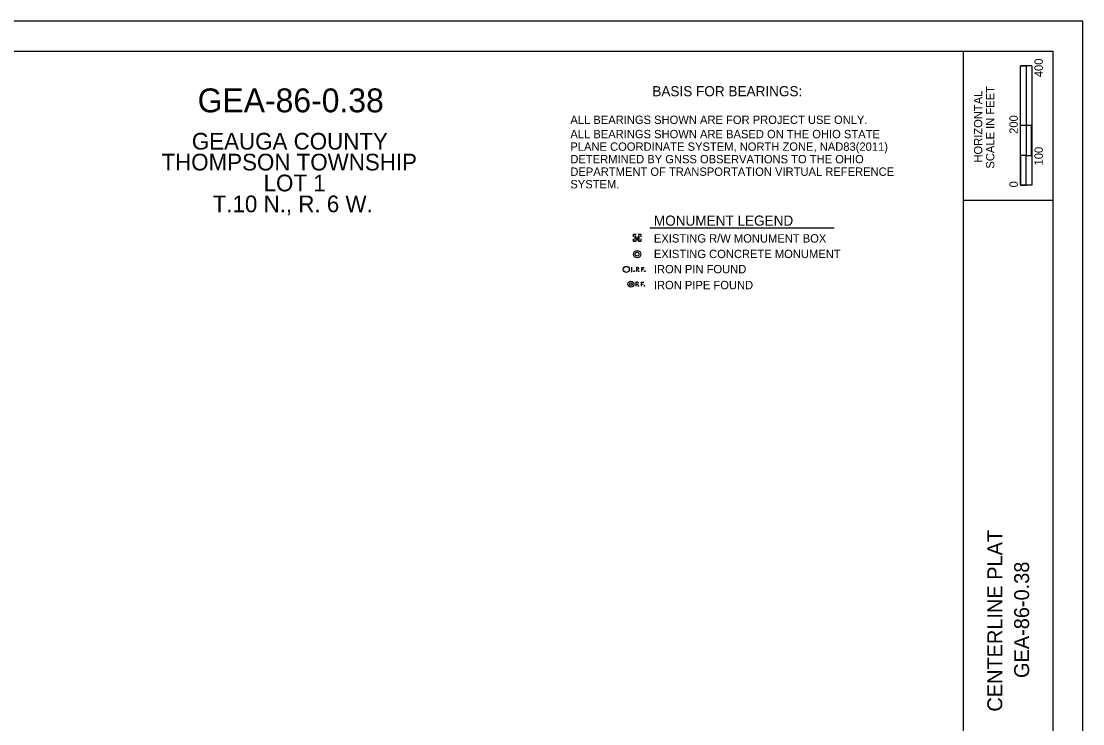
# Model space of a CAD drawing. Extents: x -0.2 to 34, y 0 to 22.
# Drawn here: x 16.2 to 34, y 10.22 to 22 of the extents above; entities that cross this region are included whole.
import ezdxf

# ---------------------------------------------------------------- set-up
doc = ezdxf.new("R2010")
doc.units = 0
for name, color, linetype in [('SH_Border', 7, 'Continuous'), ('SH_Cut_Line', 7, 'Continuous'), ('SH_Data', 7, 'Continuous'), ('SH_Text', 7, 'Continuous')]:
    doc.layers.add(name, color=color, linetype=linetype)

msp = doc.modelspace()

# ---------------------------------------------------------------- linework, layer by layer
at = {"layer": 'SH_Border'}
for p, q in [((32, 0.5), (32, 21.5)), ((32, 19), (33.5, 19))]:
    msp.add_line(p, q, dxfattribs=at)
msp.add_lwpolyline([(1.5, 21.5), (33.5, 21.5), (33.5, 0.5), (1.5, 0.5)], close=True, dxfattribs=at)
at = {"layer": 'SH_Cut_Line'}
msp.add_lwpolyline([(0, 0), (34, 0), (34, 22), (0, 22)], close=True, dxfattribs=at)
at = {"layer": 'SH_Data'}
for p, q in [((32.957, 19.25), (32.957, 21.25)), ((33.144, 21.25), (32.957, 21.25)), ((32.957, 20.25), (32.957, 21.25)), ((32.957, 21.25), (33.05, 21.25)), ((33.05, 21.25), (33.051, 21.25)), ((33.051, 21.25), (33.051, 20.25)), ((33.144, 21.25), (33.144, 19.25)), ((33.051, 20.25), (32.957, 20.25)), ((33.143, 20.25), (33.05, 20.25)), ((33.05, 20.25), (33.05, 19.75)), ((33.143, 19.75), (33.143, 20.25)), ((33.05, 19.75), (32.957, 19.75)), ((32.957, 19.75), (32.957, 19.25)), ((33.05, 19.25), (33.05, 19.75)), ((33.05, 19.75), (33.143, 19.75)), ((33.144, 19.25), (32.957, 19.25)), ((32.957, 19.25), (33.05, 19.25))]:
    msp.add_line(p, q, dxfattribs=at)
at = {"layer": 'SH_Text'}
for p, q in [((26.739, 18.534), (29.832, 18.534)), ((26.527, 18.368), (26.527, 18.368)), ((26.429, 17.873), (26.445, 17.873)), ((26.429, 17.873), (26.445, 17.873)), ((26.429, 17.806), (26.445, 17.806)), ((26.437, 17.806), (26.437, 17.873)), ((26.514, 17.841), (26.54, 17.841)), ((26.607, 17.806), (26.607, 17.873)), ((26.607, 17.873), (26.646, 17.873)), ((26.607, 17.841), (26.635, 17.841)), ((26.6, 17.559), (26.6, 17.625)), ((26.6, 17.625), (26.638, 17.625)), ((26.506, 17.593), (26.533, 17.593)), ((26.6, 17.593), (26.627, 17.593))]:
    msp.add_line(p, q, dxfattribs=at)
for points in [[(26.465, 18.383), (26.465, 18.43), (26.512, 18.43)], [(26.512, 18.305), (26.465, 18.305), (26.465, 18.352)], [(26.496, 18.326), (26.496, 18.409), (26.527, 18.326), (26.558, 18.409), (26.558, 18.326)], [(26.542, 18.43), (26.59, 18.43), (26.59, 18.383)], [(26.59, 18.352), (26.59, 18.305), (26.542, 18.305)], [(26.54, 17.873), (26.514, 17.873), (26.514, 17.806)], [(26.533, 17.625), (26.506, 17.625), (26.506, 17.559)]]:
    msp.add_lwpolyline(points, dxfattribs=at)
for centre, radius in [((26.527, 18.095), 0.0625), ((26.527, 18.095), 0.0333), ((26.345, 17.84), 0.05), ((26.477, 17.811), 0.00583), ((26.554, 17.811), 0.00583), ((26.656, 17.811), 0.00583), ((26.423, 17.592), 0.05), ((26.423, 17.592), 0.0206), ((26.547, 17.563), 0.00583), ((26.648, 17.563), 0.00583)]:
    msp.add_circle(centre, radius, dxfattribs=at)
for centre in [(26.538, 17.857), (26.531, 17.609)]:
    msp.add_arc(centre, 0.0162, 278.8803, 81.1197, dxfattribs=at)

# ---------------------------------------------------------------- texts
at = {"layer": 'SH_Data'}
for s, height, p in [('400', 0.14, (33.33, 21.062)), ('HORIZONTAL', 0.14, (32.315, 19.63)), ('SCALE IN FEET', 0.14, (32.517, 19.529)), ('200', 0.14, (32.91, 20.112)), ('100', 0.14, (33.33, 19.582)), ('0', 0.14, (32.91, 19.214)), ('CENTERLINE PLAT', 0.25, (32.65, 10.425)), ('GEA-86-0.38', 0.25, (33.1, 10.989))]:
    msp.add_text(s, height=height, rotation=90, dxfattribs=at).set_placement(p)
at = {"layer": 'SH_Text'}
for s, height, p in [('GEA-86-0.38', 0.4, (19.157, 20.473)), ('BASIS FOR BEARINGS:', 0.17, (26.782, 20.742)), ('ALL BEARINGS SHOWN ARE FOR PROJECT USE ONLY.', 0.14, (25.407, 20.278)), ('GEAUGA COUNTY', 0.28, (19.06, 19.848)), ('ALL BEARINGS SHOWN ARE BASED ON THE OHIO STATE', 0.14, (25.407, 20.038)), ('PLANE COORDINATE SYSTEM, NORTH ZONE, NAD83(2011)', 0.14, (25.407, 19.828)), ('THOMPSON TOWNSHIP', 0.28, (18.55, 19.498)), ('DETERMINED BY GNSS OBSERVATIONS TO THE OHIO', 0.14, (25.407, 19.618)), ('LOT 1', 0.28, (20.263, 19.148)), ('DEPARTMENT OF TRANSPORTATION VIRTUAL REFERENCE', 0.14, (25.407, 19.408)), ('SYSTEM.', 0.14, (25.407, 19.198)), ('T.10 N., R. 6 W.', 0.28, (19.409, 18.798)), ('MONUMENT LEGEND', 0.17, (26.808, 18.572)), ('EXISTING R/W MONUMENT BOX', 0.14, (26.808, 18.289)), ('EXISTING CONCRETE MONUMENT', 0.14, (26.808, 18.029)), ('IRON PIN FOUND', 0.14, (26.808, 17.774)), ('IRON PIPE FOUND', 0.14, (26.808, 17.507))]:
    msp.add_text(s, height=height, dxfattribs=at).set_placement(p)

doc.saveas('drawing.dxf')
